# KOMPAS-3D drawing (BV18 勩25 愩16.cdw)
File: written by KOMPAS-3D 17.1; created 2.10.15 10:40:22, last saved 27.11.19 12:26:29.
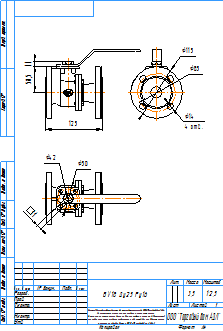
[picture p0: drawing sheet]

Sheet 1: A4, portrait

Title block, sheet 1: name: BV18 Ду25 Ру16; material: Сталь 10  ГОСТ 1050-88; mass: 3,5; sheets: 1; sheet format: A4; stored path: C:\Users\kka\KOMPAS_Work\!Trash\BV18\KOMPAS 2D\BV18 Ду100 Ру16 с голым штоком.cdw

Views: Спереди 4
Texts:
  Klimkovich
  ADL
  Рама для чертежей
  Лит-Масса-Масштаб
  Материал-Предприятие
  Масштаб
  Изм.
  Лист
  № докум.
  Подп.
  Дата
  Лит.
  Разраб.
  Пров.
  Т.контр.
  Листов
  Внимание! Данный продукт является объектом авторского права ООО «Торговый Дом АДЛ».
  Запрещается изменение, копирование, распространение
  (в том числе путем копирования на другие сайты и ресурсы в Интернете)
  или любое иное использование информации и объектов без предварительного
  согласия правообладателя (ООО «Торговый Дом АДЛ»).
  Н.контр.
  Утв.
  ООО "Торговый дом АДЛ"
  Изменение
  Номер документа
  Подпись
  Обозначение документа
  Наименование изделия
  Масса изделия по ГОСТ 2.109-73
  Порядковый номер листа
  Общее количество листов в документе
  Характер работы, выполненной лицом, подписавшим документ
  Наименование или индекс предприятия, выпускающего документ
  Инв. № подл.
  Подп. и дата
  Взам. инв. №
  Инв. № дубл.
  Инвентарный номер подлинника по ГОСТ 2.501-68
  Подпись принявшего подлинник в отдел технической документации
  Инвентарный номер подлинника, взамен которого выпущен данный подлинник
  Инвентарный номер дубликата по ГОСТ 2.502-68
  Подпись принявшего дубликат в отдел технической документации
  Справ. №
  Перв. примен.
  Обозначение документа, взамен или на основании которого выпущен данный документ
  Обозначение документа, в котором впервые записан данный документ
  Подпись лица, копировавшего чертеж
  Обозначение формата листа
  !Рама для чертежа
Dimensions and other numbers on the sheet: 125; 58,5; 11; 1:2,5; 1; 3,5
